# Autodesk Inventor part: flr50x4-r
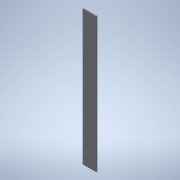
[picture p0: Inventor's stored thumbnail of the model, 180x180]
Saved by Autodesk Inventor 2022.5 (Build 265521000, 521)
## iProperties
Created: 2016-12
Part Number: flr50x4-r
Material: 一般
Document SubType Name: Modeling
Designer: imaocorp
Density: 1 g/cm^3
Appearance: 既定
Author: imaocorp
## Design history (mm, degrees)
node "flr50x4-r.x_t1"
node "flr50x4-r"
node "Base1"
